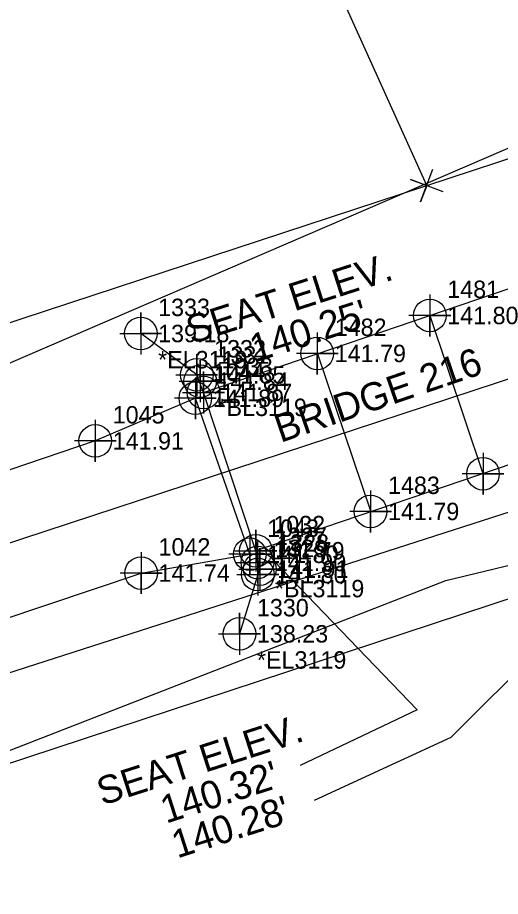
# Model space of a CAD drawing. Extents: x 2248240 to 2249086, y 672625 to 673467.
# Drawn here: x 2248591.2 to 2248660.5, y 672983.4 to 673109.5 of the extents above; entities that cross this region are included whole.
import ezdxf

# ---------------------------------------------------------------- set-up
doc = ezdxf.new("R2010")
doc.units = 0
for name, color, linetype in [('Exist Horizontal Alignment', 7, 'Continuous'), ('Exist Property Corner CELL', 7, 'Continuous'), ('Exist Property Line', 7, 'Continuous'), ('Exist Right of Way Line', 7, 'Continuous'), ('Exist Roads EOP', 7, 'Continuous'), ('Exist Roads EOP Cogo Elevation', 7, 'Continuous'), ('Exist Roads EOP Cogo Number', 7, 'Continuous'), ('Exist Roads EOP Cogo Point CELL', 7, 'Continuous'), ('Exist Structure Major Bridge Seam', 7, 'Continuous'), ('Exist Structure Major Bridge Seam Cogo Elevation', 7, 'Continuous'), ('Exist Structure Major Bridge Seam Cogo Number', 7, 'Continuous'), ('Exist Structure Major Bridge Seam Cogo Point CELL', 7, 'Continuous'), ('Exist Structure Major Bridge WW', 7, 'Continuous'), ('Exist Structure Major Bridge WW Cogo Comment', 7, 'Continuous'), ('Exist Structure Major Bridge WW Cogo Elevation', 7, 'Continuous'), ('Exist Structure Major Bridge WW Cogo Number', 7, 'Continuous'), ('Exist Structure Major Bridge WW Cogo Point CELL', 7, 'Continuous'), ('Exist Structure Major Deck Tunnel Box Culvert', 7, 'Continuous'), ('Exist Structure Major Deck Tunnel Box Culvert Cogo Elevation', 7, 'Continuous'), ('Exist Structure Major Deck Tunnel Box Culvert Cogo Number', 7, 'Continuous'), ('Exist Structure Major Deck Tunnel Box Culvert Cogo Point CELL', 7, 'Continuous'), ('Exist Structure Major Deck Tunnel Box Culvert Leader', 7, 'Continuous'), ('Exist Structure Major Deck Tunnel Box Culvert Text', 7, 'Continuous'), ('Exist Utilities Water UG Line SUE LOS C', 7, 'Continuous'), ('Exist Vegetation Woods Line', 7, 'Continuous')]:
    doc.layers.add(name, color=color, linetype=linetype)

msp = doc.modelspace()

# ---------------------------------------------------------------- linework, layer by layer
at = {"layer": 'Exist Horizontal Alignment'}
msp.add_line((2248277.37, 672931.22), (2248730.23, 673080.25), dxfattribs=at)
at = {"layer": 'Exist Property Corner CELL'}
msp.add_line((2248649.91, 673085.4), (2248649.91, 673085.4), dxfattribs=at)
msp.add_lwpolyline([(2248652.25, 673084.51), (2248647.57, 673086.28), (2248649.91, 673085.4), (2248649.03, 673083.06), (2248650.8, 673087.73)], dxfattribs=at)
at = {"layer": 'Exist Property Line'}
msp.add_line((2248649.91, 673085.4), (2248493.76, 673431.96), dxfattribs=at)
at = {"layer": 'Exist Right of Way Line'}
for p, q in [((2248716.39, 673107.27), (2248267.99, 672959.72)), ((2248286.75, 672902.73), (2248735.14, 673050.28))]:
    msp.add_line(p, q, dxfattribs=at)
at = {"layer": 'Exist Roads EOP'}
msp.add_lwpolyline([(2248280.35, 672921.48), (2248327.15, 672936.49), (2248374.55, 672952.25), (2248420.47, 672967.21), (2248467.96, 672983.23), (2248515.03, 672998.64), (2248561.42, 673013.84), (2248608.93, 673029.8), (2248624.52, 673032.49), (2248616.71, 673054.88), (2248602.35, 673048.76), (2248555.39, 673032.83), (2248509.31, 673017.92), (2248462.07, 673002.36), (2248414.6, 672986.98), (2248368.35, 672972.05), (2248320.86, 672956.23), (2248274.38, 672940.97)], dxfattribs=at)
at = {"layer": 'Exist Roads EOP Cogo Point CELL'}
for points in [[(2248616.71, 673057.88), (2248616.71, 673051.88), (2248616.71, 673054.88), (2248619.71, 673054.88), (2248613.71, 673054.88)], [(2248602.35, 673051.76), (2248602.35, 673045.76), (2248602.35, 673048.76), (2248605.35, 673048.76), (2248599.35, 673048.76)], [(2248624.52, 673035.49), (2248624.52, 673029.49), (2248624.52, 673032.49), (2248627.52, 673032.49), (2248621.52, 673032.49)], [(2248608.93, 673032.8), (2248608.93, 673026.8), (2248608.93, 673029.8), (2248611.93, 673029.8), (2248605.93, 673029.8)]]:
    msp.add_lwpolyline(points, dxfattribs=at)
for centre in [(2248616.71, 673054.88), (2248602.35, 673048.76), (2248624.52, 673032.49), (2248608.93, 673029.8)]:
    msp.add_circle(centre, 2.34, dxfattribs=at)
at = {"layer": 'Exist Structure Major Bridge Seam'}
for p, q in [((2248650.36, 673066.74), (2248657.98, 673044.07)), ((2248634.23, 673061.25), (2248641.87, 673038.6))]:
    msp.add_line(p, q, dxfattribs=at)
at = {"layer": 'Exist Structure Major Bridge Seam Cogo Point CELL'}
for points in [[(2248650.36, 673069.76), (2248650.36, 673063.76), (2248650.36, 673066.76), (2248653.36, 673066.76), (2248647.36, 673066.76)], [(2248634.21, 673064.31), (2248634.21, 673058.31), (2248634.21, 673061.31), (2248637.21, 673061.31), (2248631.21, 673061.31)], [(2248657.99, 673047.05), (2248657.99, 673041.05), (2248657.99, 673044.05), (2248660.99, 673044.05), (2248654.99, 673044.05)], [(2248641.86, 673041.64), (2248641.86, 673035.64), (2248641.86, 673038.64), (2248644.86, 673038.64), (2248638.86, 673038.64)]]:
    msp.add_lwpolyline(points, dxfattribs=at)
for centre in [(2248650.36, 673066.76), (2248634.21, 673061.31), (2248657.99, 673044.05), (2248641.86, 673038.64)]:
    msp.add_circle(centre, 2.34, dxfattribs=at)
at = {"layer": 'Exist Structure Major Bridge WW'}
for points in [[(2248617.89, 673055.7), (2248616.91, 673058.23), (2248608.87, 673064.17)], [(2248625.4, 673033), (2248625.95, 673030.36), (2248625.68, 673029.58), (2248623.05, 673021.08)]]:
    msp.add_lwpolyline(points, dxfattribs=at)
at = {"layer": 'Exist Structure Major Bridge WW Cogo Point CELL'}
for points in [[(2248605.87, 673064.17), (2248611.87, 673064.17), (2248608.87, 673064.17), (2248608.87, 673067.17), (2248608.87, 673061.17)], [(2248613.91, 673058.23), (2248619.91, 673058.23), (2248616.91, 673058.23), (2248616.91, 673061.23), (2248616.91, 673055.23)], [(2248614.39, 673057.33), (2248620.39, 673057.33), (2248617.39, 673057.33), (2248617.39, 673060.33), (2248617.39, 673054.33)], [(2248622.63, 673031.32), (2248628.63, 673031.32), (2248625.63, 673031.32), (2248625.63, 673034.32), (2248625.63, 673028.32)], [(2248622.95, 673030.36), (2248628.95, 673030.36), (2248625.95, 673030.36), (2248625.95, 673033.36), (2248625.95, 673027.36)], [(2248622.68, 673029.58), (2248628.68, 673029.58), (2248625.68, 673029.58), (2248625.68, 673032.58), (2248625.68, 673026.58)], [(2248620.05, 673021.08), (2248626.05, 673021.08), (2248623.05, 673021.08), (2248623.05, 673024.08), (2248623.05, 673018.08)]]:
    msp.add_lwpolyline(points, dxfattribs=at)
for centre in [(2248608.87, 673064.17), (2248616.91, 673058.23), (2248617.39, 673057.33), (2248625.63, 673031.32), (2248625.68, 673029.58), (2248625.95, 673030.36), (2248623.05, 673021.08)]:
    msp.add_circle(centre, 2.34, dxfattribs=at)
at = {"layer": 'Exist Structure Major Deck Tunnel Box Culvert'}
msp.add_lwpolyline([(2248706.73, 673060.62), (2248625.4, 673033), (2248617.89, 673055.7), (2248698.88, 673083.24)], dxfattribs=at)
at = {"layer": 'Exist Structure Major Deck Tunnel Box Culvert Cogo Point CELL'}
for points in [[(2248614.89, 673055.7), (2248620.89, 673055.7), (2248617.89, 673055.7), (2248617.89, 673058.7), (2248617.89, 673052.7)], [(2248622.4, 673033), (2248628.4, 673033), (2248625.4, 673033), (2248625.4, 673036), (2248625.4, 673030)]]:
    msp.add_lwpolyline(points, dxfattribs=at)
for centre in [(2248617.89, 673055.7), (2248625.4, 673033)]:
    msp.add_circle(centre, 2.34, dxfattribs=at)
at = {"layer": 'Exist Structure Major Deck Tunnel Box Culvert Leader'}
for points in [[(2248704.39, 673057.04), (2248653.36, 673006.18), (2248633.75, 672997.17)], [(2248627.94, 673031.61), (2248648.56, 673010.19), (2248631.75, 673002.18)]]:
    msp.add_lwpolyline(points, dxfattribs=at)
at = {"layer": 'Exist Utilities Water UG Line SUE LOS C'}
msp.add_line((2248530.3, 672996.29), (2248853.08, 673100.11), dxfattribs=at)
at = {"layer": 'Exist Vegetation Woods Line'}
for points in [[(2248682.79, 673177.86), (2248667.65, 673115.13), (2248663.64, 673091.64), (2248570.37, 673051.47), (2248460.42, 673013.15), (2248368.39, 672986.57), (2248259.41, 672951.1)], [(2248274.03, 672898.01), (2248385.83, 672936.02), (2248488.06, 672971.87), (2248541.49, 672985.46), (2248652.67, 673028.73), (2248668.11, 673032.44), (2248686.33, 672939.73)]]:
    msp.add_lwpolyline(points, dxfattribs=at)

# ---------------------------------------------------------------- texts
at = {"layer": 'Exist Roads EOP Cogo Elevation'}
for s, p in [('141.89', (2248619.21, 673053.63)), ('141.91', (2248604.85, 673047.51)), ('141.80', (2248627.02, 673031.24)), ('141.74', (2248611.43, 673028.55))]:
    msp.add_text(s, height=2.5, dxfattribs=at).set_placement(p)
at = {"layer": 'Exist Roads EOP Cogo Number'}
for s, p in [('1044', (2248619.21, 673057.38)), ('1045', (2248604.85, 673051.26)), ('1043', (2248627.02, 673034.99)), ('1042', (2248611.43, 673032.3))]:
    msp.add_text(s, height=2.5, dxfattribs=at).set_placement(p)
at = {"layer": 'Exist Structure Major Bridge Seam Cogo Elevation'}
for s, p in [('141.80', (2248652.86, 673065.51)), ('141.79', (2248636.71, 673060.06)), ('141.79', (2248644.36, 673037.39))]:
    msp.add_text(s, height=2.5, dxfattribs=at).set_placement(p)
at = {"layer": 'Exist Structure Major Bridge Seam Cogo Number'}
for s, p in [('1481', (2248652.86, 673069.26)), ('1482', (2248636.71, 673063.81)), ('1483', (2248644.36, 673041.14))]:
    msp.add_text(s, height=2.5, dxfattribs=at).set_placement(p)
at = {"layer": 'Exist Structure Major Bridge WW Cogo Comment'}
for s, p in [('*EL3119', (2248611.37, 673059.17)), ('*BL3119', (2248619.89, 673052.33)), ('*BL3119', (2248628.13, 673026.32)), ('*EL3119', (2248625.55, 673016.08))]:
    msp.add_text(s, height=2.5, dxfattribs=at).set_placement(p)
at = {"layer": 'Exist Structure Major Bridge WW Cogo Elevation'}
for s, p in [('139.18', (2248611.37, 673062.92)), ('141.85', (2248619.41, 673056.98)), ('141.84', (2248619.89, 673056.08)), ('141.90', (2248628.13, 673030.07)), ('141.80', (2248628.18, 673028.33)), ('141.91', (2248628.45, 673029.11)), ('138.23', (2248625.55, 673019.83))]:
    msp.add_text(s, height=2.5, dxfattribs=at).set_placement(p)
at = {"layer": 'Exist Structure Major Bridge WW Cogo Number'}
for s, p in [('1333', (2248611.37, 673066.67)), ('1332', (2248619.41, 673060.73)), ('1331', (2248619.89, 673059.83)), ('1327', (2248628.13, 673033.82)), ('1329', (2248628.18, 673032.08)), ('1328', (2248628.45, 673032.86)), ('1330', (2248625.55, 673023.58))]:
    msp.add_text(s, height=2.5, dxfattribs=at).set_placement(p)
at = {"layer": 'Exist Structure Major Deck Tunnel Box Culvert Cogo Elevation'}
for s, p in [('141.87', (2248620.39, 673054.45)), ('141.79', (2248627.9, 673031.75))]:
    msp.add_text(s, height=2.5, dxfattribs=at).set_placement(p)
at = {"layer": 'Exist Structure Major Deck Tunnel Box Culvert Cogo Number'}
for s, p in [('1033', (2248620.39, 673058.2)), ('1032', (2248627.9, 673035.5))]:
    msp.add_text(s, height=2.5, dxfattribs=at).set_placement(p)
at = {"layer": 'Exist Structure Major Deck Tunnel Box Culvert Text'}
for s, rotation, p in [('SEAT ELEV.', 17.7975, (2248616.18, 673062.61)), ("140.25'", 17.7975, (2248625.31, 673060.02)), ('BRIDGE 216', 18.8635, (2248628.93, 673048.47)), ('SEAT ELEV.', 17.7975, (2248603.37, 672996.41)), ("140.32'", 17.7975, (2248612.5, 672993.83)), ("140.28'", 17.7975, (2248614.11, 672988.83))]:
    msp.add_text(s, height=4, rotation=rotation, dxfattribs=at).set_placement(p)

doc.saveas('drawing.dxf')
